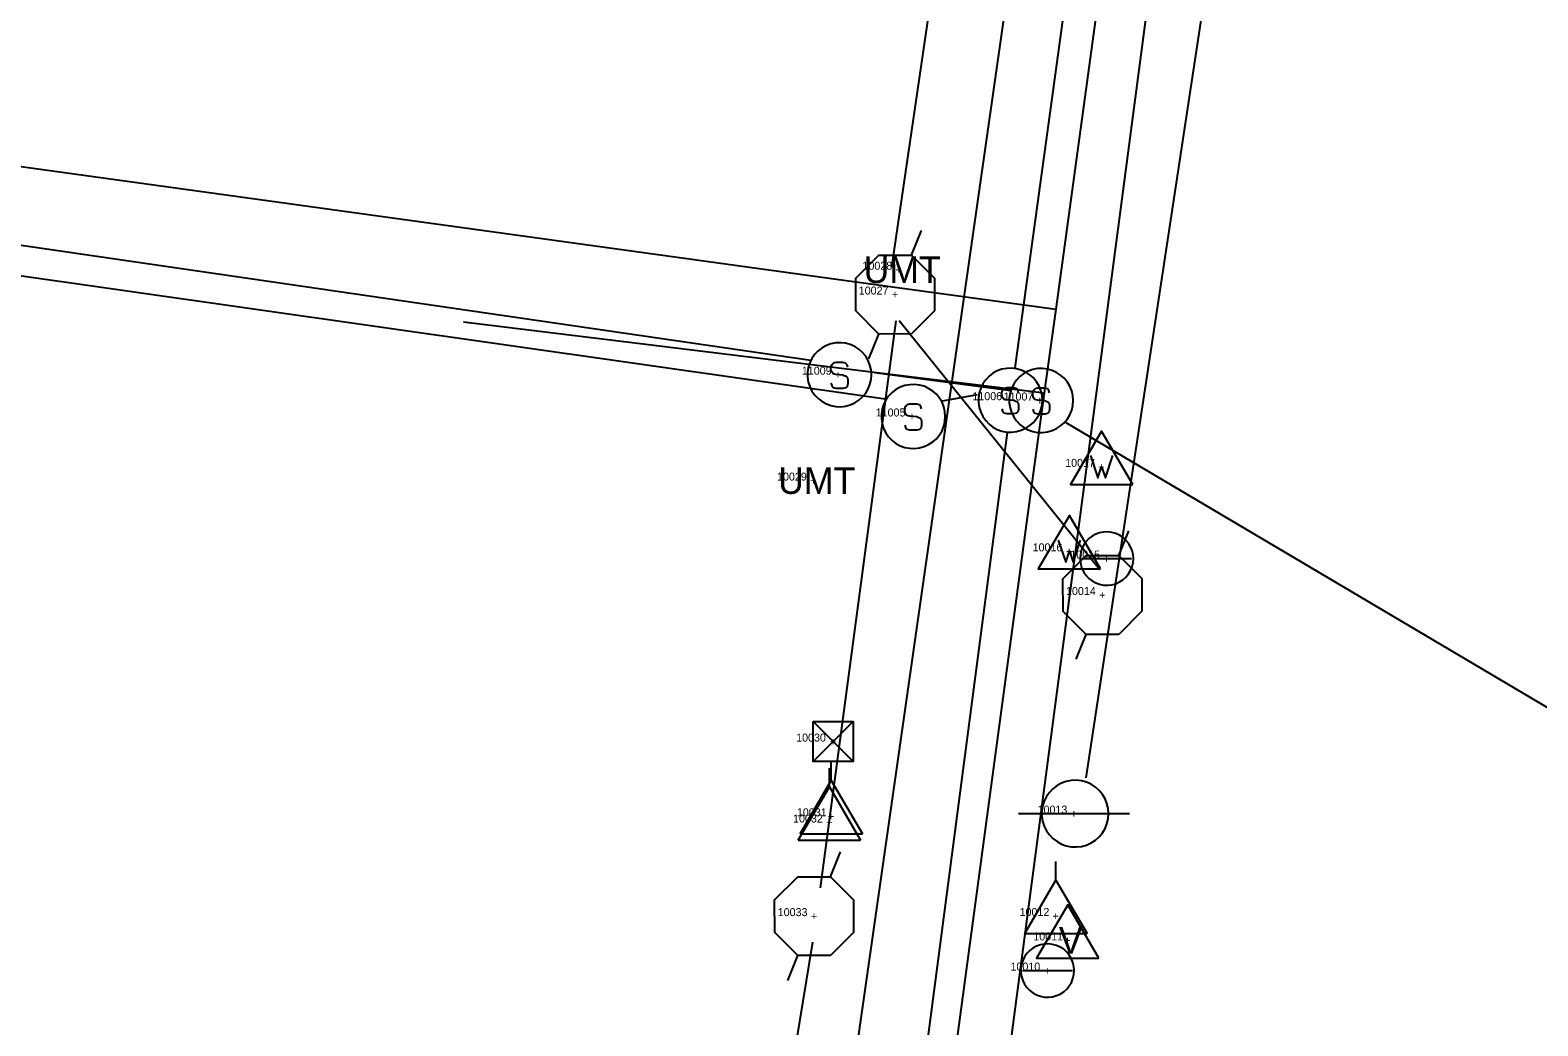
# Model space of a CAD drawing. Extents: x 1795905 to 1799611, y 243768 to 252016.
# Drawn here: x 1797344.4 to 1797626.9, y 244659.6 to 244846.2 of the extents above; entities that cross this region are included whole.
import ezdxf

# ---------------------------------------------------------------- set-up
doc = ezdxf.new("R2010")
doc.units = 0
for name, color, linetype in [('Level 50', 7, 'Continuous'), ('LS-SURVEY POINT', 7, 'Continuous'), ('OHUT', 7, 'Continuous'), ('OHUTTXT', 7, 'Continuous'), ('UGUT', 7, 'Continuous'), ('UGUTTXT', 7, 'Continuous')]:
    doc.layers.add(name, color=color, linetype=linetype)

msp = doc.modelspace()

# ---------------------------------------------------------------- linework, layer by layer
at = {"layer": 'Level 50'}
for p, q in [((1797509.53, 244804.03), (1797511.43, 244808.65)), ((1797501.54, 244784.61), (1797503.44, 244789.23)), ((1797548.38, 244747.73), (1797550.28, 244752.35)), ((1797540.4, 244728.3), (1797542.3, 244732.93)), ((1797494.34, 244687.56), (1797496.25, 244692.19)), ((1797486.36, 244668.14), (1797488.26, 244672.77))]:
    msp.add_line(p, q, dxfattribs=at)
for points in [[(1797509.57, 244789.25), (1797503.44, 244789.23), (1797499.1, 244793.55), (1797499.09, 244799.67), (1797503.4, 244804.01), (1797509.53, 244804.03), (1797513.87, 244799.71), (1797513.89, 244793.59)], [(1797548.42, 244732.95), (1797542.3, 244732.93), (1797537.96, 244737.25), (1797537.94, 244743.37), (1797542.26, 244747.71), (1797548.38, 244747.73), (1797552.72, 244743.41), (1797552.74, 244737.29)], [(1797494.38, 244672.78), (1797488.26, 244672.77), (1797483.92, 244677.08), (1797483.9, 244683.21), (1797488.22, 244687.55), (1797494.34, 244687.56), (1797498.69, 244683.25), (1797498.7, 244677.12)]]:
    msp.add_lwpolyline(points, close=True, dxfattribs=at)
at = {"layer": 'OHUT'}
for p, q in [((1797494.51, 244705.57), (1797494.51, 244709.07)), ((1797494.17, 244704.41), (1797494.17, 244707.91)), ((1797529.59, 244699.38), (1797550.43, 244699.38)), ((1797488.34, 244694.41), (1797500.01, 244694.41)), ((1797488.68, 244695.57), (1797500.35, 244695.57)), ((1797536.63, 244686.89), (1797536.63, 244690.39)), ((1797530.8, 244676.89), (1797542.46, 244676.89))]:
    msp.add_line(p, q, dxfattribs=at)
for points in [[(1797488.68, 244695.57), (1797494.51, 244705.57), (1797500.35, 244695.57)], [(1797488.34, 244694.41), (1797494.17, 244704.41), (1797500.01, 244694.41)], [(1797530.8, 244676.89), (1797536.63, 244686.89), (1797542.46, 244676.89)]]:
    msp.add_lwpolyline(points, dxfattribs=at)
msp.add_lwpolyline([(1797546.47, 244699.38), (1797546.4, 244700.33), (1797546.18, 244701.26), (1797545.82, 244702.15), (1797545.33, 244702.97), (1797544.72, 244703.71), (1797544.01, 244704.35), (1797543.21, 244704.87), (1797542.33, 244705.26), (1797541.41, 244705.51), (1797540.46, 244705.62), (1797539.5, 244705.58), (1797538.56, 244705.4), (1797537.66, 244705.08), (1797536.82, 244704.62), (1797536.06, 244704.04), (1797535.4, 244703.35), (1797534.85, 244702.57), (1797534.42, 244701.71), (1797534.13, 244700.8), (1797533.99, 244699.85), (1797533.99, 244698.9), (1797534.13, 244697.95), (1797534.42, 244697.04), (1797534.85, 244696.18), (1797535.4, 244695.4), (1797536.06, 244694.71), (1797536.82, 244694.13), (1797537.66, 244693.67), (1797538.56, 244693.35), (1797539.5, 244693.17), (1797540.46, 244693.13), (1797541.41, 244693.24), (1797542.33, 244693.49), (1797543.21, 244693.89), (1797544.01, 244694.4), (1797544.72, 244695.04), (1797545.33, 244695.78), (1797545.82, 244696.6), (1797546.18, 244697.49), (1797546.4, 244698.42)], close=True, dxfattribs=at)
at = {"layer": 'OHUTTXT'}
for p, q in [((1797505.88, 244801.76), (1797519.74, 244896.6)), ((1797542.26, 244706.1), (1797564.52, 244852.58)), ((1797492.48, 244685.45), (1797506.67, 244791.73)), ((1797507.22, 244791.74), (1797544.87, 244745.14)), ((1797477.37, 244591.55), (1797491.04, 244675.3))]:
    msp.add_line(p, q, dxfattribs=at)
at = {"layer": 'UGUT'}
for p, q in [((1797494.46, 244782.57), (1797494.46, 244783.02)), ((1797494.59, 244782.12), (1797494.46, 244782.57)), ((1797494.84, 244781.8), (1797494.59, 244782.12)), ((1797495.36, 244781.67), (1797494.84, 244781.8)), ((1797496.76, 244781.55), (1797495.36, 244781.67)), ((1797497.21, 244783.79), (1797496.7, 244783.91)), ((1797497.47, 244783.47), (1797497.21, 244783.79)), ((1797497.6, 244783.02), (1797497.47, 244783.47)), ((1797494.46, 244780.01), (1797494.59, 244779.56)), ((1797494.59, 244779.56), (1797494.84, 244779.24)), ((1797494.84, 244779.24), (1797495.36, 244779.11)), ((1797495.36, 244779.11), (1797496.76, 244779.11)), ((1797496.76, 244781.55), (1797497.28, 244781.35)), ((1797496.76, 244779.11), (1797497.28, 244779.24)), ((1797497.6, 244781.03), (1797497.28, 244781.35)), ((1797497.28, 244779.24), (1797497.6, 244779.56)), ((1797497.66, 244780.59), (1797497.6, 244781.03)), ((1797497.6, 244779.56), (1797497.66, 244780.01)), ((1797497.66, 244780.01), (1797497.66, 244780.59)), ((1797529.25, 244779.01), (1797528.73, 244779.14)), ((1797529.5, 244778.69), (1797529.25, 244779.01)), ((1797535.03, 244778.95), (1797534.51, 244779.08)), ((1797535.28, 244778.63), (1797535.03, 244778.95)), ((1797511.05, 244775.96), (1797510.54, 244776.09)), ((1797526.49, 244777.79), (1797526.49, 244778.24)), ((1797526.62, 244777.35), (1797526.49, 244777.79)), ((1797526.88, 244777.03), (1797526.62, 244777.35)), ((1797527.39, 244776.9), (1797526.88, 244777.03)), ((1797528.8, 244776.77), (1797527.39, 244776.9)), ((1797528.8, 244776.77), (1797529.31, 244776.58)), ((1797529.63, 244776.26), (1797529.31, 244776.58)), ((1797529.63, 244778.24), (1797529.5, 244778.69)), ((1797529.69, 244775.81), (1797529.63, 244776.26)), ((1797532.27, 244777.74), (1797532.27, 244778.18)), ((1797532.4, 244777.29), (1797532.27, 244777.74)), ((1797532.66, 244776.97), (1797532.4, 244777.29)), ((1797533.17, 244776.84), (1797532.66, 244776.97)), ((1797534.58, 244776.71), (1797533.17, 244776.84)), ((1797534.58, 244776.71), (1797535.09, 244776.52)), ((1797535.41, 244776.2), (1797535.09, 244776.52)), ((1797535.41, 244778.18), (1797535.28, 244778.63)), ((1797535.47, 244775.75), (1797535.41, 244776.2)), ((1797508.3, 244774.74), (1797508.3, 244775.19)), ((1797508.43, 244774.29), (1797508.3, 244774.74)), ((1797508.69, 244773.97), (1797508.43, 244774.29)), ((1797509.2, 244773.85), (1797508.69, 244773.97)), ((1797510.61, 244773.72), (1797509.2, 244773.85)), ((1797510.61, 244773.72), (1797511.12, 244773.53)), ((1797511.31, 244775.64), (1797511.05, 244775.96)), ((1797511.44, 244773.21), (1797511.12, 244773.53)), ((1797511.44, 244775.19), (1797511.31, 244775.64)), ((1797511.5, 244772.76), (1797511.44, 244773.21)), ((1797526.49, 244775.23), (1797526.62, 244774.79)), ((1797526.62, 244774.79), (1797526.88, 244774.47)), ((1797526.88, 244774.47), (1797527.39, 244774.34)), ((1797527.39, 244774.34), (1797528.8, 244774.34)), ((1797528.8, 244774.34), (1797529.31, 244774.47)), ((1797529.31, 244774.47), (1797529.63, 244774.79)), ((1797529.63, 244774.79), (1797529.69, 244775.23)), ((1797529.69, 244775.23), (1797529.69, 244775.81)), ((1797532.27, 244775.18), (1797532.4, 244774.73)), ((1797532.4, 244774.73), (1797532.66, 244774.41)), ((1797532.66, 244774.41), (1797533.17, 244774.28)), ((1797533.17, 244774.28), (1797534.58, 244774.28)), ((1797534.58, 244774.28), (1797535.09, 244774.41)), ((1797535.09, 244774.41), (1797535.41, 244774.73)), ((1797535.41, 244774.73), (1797535.47, 244775.18)), ((1797535.47, 244775.18), (1797535.47, 244775.75)), ((1797508.3, 244772.18), (1797508.43, 244771.73)), ((1797508.43, 244771.73), (1797508.69, 244771.41)), ((1797508.69, 244771.41), (1797509.2, 244771.29)), ((1797509.2, 244771.29), (1797510.61, 244771.29)), ((1797510.61, 244771.29), (1797511.12, 244771.41)), ((1797511.12, 244771.41), (1797511.44, 244771.73)), ((1797511.44, 244771.73), (1797511.5, 244772.18)), ((1797511.5, 244772.18), (1797511.5, 244772.76)), ((1797541.46, 244747.16), (1797550.8, 244747.16)), ((1797491.13, 244716.62), (1797498.63, 244709.12)), ((1797498.63, 244716.62), (1797491.13, 244709.12)), ((1797530.38, 244669.97), (1797539.71, 244669.97))]:
    msp.add_line(p, q, dxfattribs=at)
for points in [[(1797502.05, 244781.61), (1797501.98, 244782.52), (1797501.77, 244783.42), (1797501.43, 244784.27), (1797500.96, 244785.06), (1797500.37, 244785.77), (1797499.69, 244786.38), (1797498.92, 244786.88), (1797498.08, 244787.25), (1797497.19, 244787.5), (1797496.28, 244787.6), (1797495.36, 244787.57), (1797494.46, 244787.39), (1797493.6, 244787.08), (1797492.79, 244786.64), (1797492.06, 244786.09), (1797491.42, 244785.43), (1797490.89, 244784.67), (1797490.49, 244783.85), (1797490.21, 244782.97), (1797490.07, 244782.07), (1797490.07, 244781.15), (1797490.21, 244780.24), (1797490.49, 244779.37), (1797490.89, 244778.54), (1797491.42, 244777.79), (1797492.06, 244777.13), (1797492.79, 244776.57), (1797493.6, 244776.13), (1797494.46, 244775.82), (1797495.36, 244775.65), (1797496.28, 244775.61), (1797497.19, 244775.72), (1797498.08, 244775.96), (1797498.92, 244776.34), (1797499.69, 244776.84), (1797500.37, 244777.45), (1797500.96, 244778.16), (1797501.43, 244778.95), (1797501.77, 244779.8), (1797501.98, 244780.69)], [(1797534.09, 244776.83), (1797534.02, 244777.75), (1797533.81, 244778.64), (1797533.46, 244779.49), (1797532.99, 244780.28), (1797532.41, 244780.99), (1797531.72, 244781.6), (1797530.95, 244782.1), (1797530.11, 244782.48), (1797529.23, 244782.72), (1797528.32, 244782.83), (1797527.4, 244782.79), (1797526.5, 244782.62), (1797525.63, 244782.31), (1797524.82, 244781.87), (1797524.09, 244781.31), (1797523.46, 244780.65), (1797522.93, 244779.9), (1797522.52, 244779.07), (1797522.24, 244778.2), (1797522.1, 244777.29), (1797522.1, 244776.37), (1797522.24, 244775.46), (1797522.52, 244774.59), (1797522.93, 244773.77), (1797523.46, 244773.01), (1797524.09, 244772.35), (1797524.82, 244771.8), (1797525.63, 244771.36), (1797526.5, 244771.05), (1797527.4, 244770.87), (1797528.32, 244770.84), (1797529.23, 244770.94), (1797530.11, 244771.19), (1797530.95, 244771.56), (1797531.72, 244772.06), (1797532.41, 244772.67), (1797532.99, 244773.38), (1797533.46, 244774.17), (1797533.81, 244775.02), (1797534.02, 244775.92)], [(1797539.87, 244776.77), (1797539.79, 244777.69), (1797539.59, 244778.58), (1797539.24, 244779.44), (1797538.77, 244780.23), (1797538.19, 244780.94), (1797537.5, 244781.55), (1797536.73, 244782.05), (1797535.89, 244782.42), (1797535.01, 244782.67), (1797534.09, 244782.77), (1797533.18, 244782.74), (1797532.28, 244782.56), (1797531.41, 244782.25), (1797530.6, 244781.81), (1797529.87, 244781.25), (1797529.24, 244780.59), (1797528.71, 244779.84), (1797528.3, 244779.02), (1797528.02, 244778.14), (1797527.88, 244777.23), (1797527.88, 244776.32), (1797528.02, 244775.41), (1797528.3, 244774.53), (1797528.71, 244773.71), (1797529.24, 244772.96), (1797529.87, 244772.3), (1797530.6, 244771.74), (1797531.41, 244771.3), (1797532.28, 244770.99), (1797533.18, 244770.81), (1797534.09, 244770.78), (1797535.01, 244770.89), (1797535.89, 244771.13), (1797536.73, 244771.5), (1797537.5, 244772), (1797538.19, 244772.61), (1797538.77, 244773.32), (1797539.24, 244774.11), (1797539.59, 244774.96), (1797539.79, 244775.86)], [(1797515.89, 244773.78), (1797515.82, 244774.7), (1797515.61, 244775.59), (1797515.27, 244776.44), (1797514.8, 244777.23), (1797514.22, 244777.94), (1797513.53, 244778.55), (1797512.76, 244779.05), (1797511.92, 244779.43), (1797511.04, 244779.67), (1797510.12, 244779.78), (1797509.21, 244779.74), (1797508.3, 244779.57), (1797507.44, 244779.26), (1797506.63, 244778.82), (1797505.9, 244778.26), (1797505.26, 244777.6), (1797504.74, 244776.85), (1797504.33, 244776.02), (1797504.05, 244775.15), (1797503.91, 244774.24), (1797503.91, 244773.32), (1797504.05, 244772.41), (1797504.33, 244771.54), (1797504.74, 244770.71), (1797505.26, 244769.96), (1797505.9, 244769.3), (1797506.63, 244768.74), (1797507.44, 244768.31), (1797508.3, 244767.99), (1797509.21, 244767.82), (1797510.12, 244767.79), (1797511.04, 244767.89), (1797511.92, 244768.13), (1797512.76, 244768.51), (1797513.53, 244769.01), (1797514.22, 244769.62), (1797514.8, 244770.33), (1797515.27, 244771.12), (1797515.61, 244771.97), (1797515.82, 244772.86)], [(1797551.01, 244761.04), (1797545.18, 244771.04), (1797539.35, 244761.04)], [(1797544.98, 244745.21), (1797539.14, 244755.21), (1797533.31, 244745.21)], [(1797551.13, 244747.16), (1797551.07, 244747.92), (1797550.9, 244748.67), (1797550.61, 244749.38), (1797550.22, 244750.04), (1797549.73, 244750.63), (1797549.16, 244751.14), (1797548.52, 244751.55), (1797547.82, 244751.86), (1797547.08, 244752.07), (1797546.32, 244752.15), (1797545.56, 244752.13), (1797544.81, 244751.98), (1797544.09, 244751.72), (1797543.41, 244751.36), (1797542.8, 244750.89), (1797542.27, 244750.34), (1797541.83, 244749.71), (1797541.49, 244749.03), (1797541.26, 244748.3), (1797541.15, 244747.54), (1797541.15, 244746.78), (1797541.26, 244746.02), (1797541.49, 244745.29), (1797541.83, 244744.6), (1797542.27, 244743.98), (1797542.8, 244743.43), (1797543.41, 244742.96), (1797544.09, 244742.6), (1797544.81, 244742.34), (1797545.56, 244742.19), (1797546.32, 244742.16), (1797547.08, 244742.25), (1797547.82, 244742.45), (1797548.52, 244742.77), (1797549.16, 244743.18), (1797549.73, 244743.69), (1797550.22, 244744.28), (1797550.61, 244744.94), (1797550.9, 244745.65), (1797551.07, 244746.4)], [(1797491.13, 244716.62), (1797498.63, 244716.62), (1797498.63, 244709.12), (1797491.13, 244709.12)], [(1797544.66, 244672.29), (1797538.83, 244682.29), (1797533, 244672.29)], [(1797540.04, 244669.97), (1797539.99, 244670.73), (1797539.81, 244671.48), (1797539.52, 244672.19), (1797539.13, 244672.85), (1797538.65, 244673.44), (1797538.07, 244673.95), (1797537.43, 244674.36), (1797536.73, 244674.68), (1797536, 244674.88), (1797535.24, 244674.97), (1797534.47, 244674.94), (1797533.72, 244674.79), (1797533, 244674.53), (1797532.32, 244674.17), (1797531.72, 244673.7), (1797531.19, 244673.15), (1797530.75, 244672.53), (1797530.41, 244671.84), (1797530.18, 244671.11), (1797530.06, 244670.35), (1797530.06, 244669.59), (1797530.18, 244668.83), (1797530.41, 244668.1), (1797530.75, 244667.42), (1797531.19, 244666.79), (1797531.72, 244666.24), (1797532.32, 244665.77), (1797533, 244665.41), (1797533.72, 244665.15), (1797534.47, 244665), (1797535.24, 244664.98), (1797536, 244665.06), (1797536.73, 244665.27), (1797537.43, 244665.58), (1797538.07, 244665.99), (1797538.65, 244666.5), (1797539.13, 244667.09), (1797539.52, 244667.75), (1797539.81, 244668.46), (1797539.99, 244669.21)]]:
    msp.add_lwpolyline(points, close=True, dxfattribs=at)
for points in [[(1797494.46, 244783.02), (1797494.59, 244783.47), (1797494.84, 244783.79)], [(1797496.7, 244783.91), (1797495.36, 244783.91), (1797494.84, 244783.79)], [(1797526.49, 244778.24), (1797526.62, 244778.69), (1797526.88, 244779.01)], [(1797528.73, 244779.14), (1797527.39, 244779.14), (1797526.88, 244779.01)], [(1797532.27, 244778.18), (1797532.4, 244778.63), (1797532.66, 244778.95)], [(1797534.51, 244779.08), (1797533.17, 244779.08), (1797532.66, 244778.95)], [(1797510.54, 244776.09), (1797509.2, 244776.09), (1797508.69, 244775.96)], [(1797508.3, 244775.19), (1797508.43, 244775.64), (1797508.69, 244775.96)], [(1797543.1, 244766.46), (1797544.49, 244762.29), (1797545.18, 244764.37), (1797545.88, 244762.29), (1797547.26, 244766.46)], [(1797537.06, 244750.63), (1797538.45, 244746.46), (1797539.14, 244748.55), (1797539.84, 244746.46), (1797541.23, 244750.63)]]:
    msp.add_lwpolyline(points, dxfattribs=at)
at = {"layer": 'UGUTTXT'}
for p, q in [((1797473.84, 244476.69), (1797534.35, 244900.9)), ((1797504.59, 244777.04), (1797165.71, 244825.29)), ((1797490.66, 244784.27), (1797217.66, 244824.02)), ((1797502.64, 244781.99), (1797528.19, 244778.64)), ((1797521.85, 244777.82), (1797515.33, 244776.64)), ((1797481.84, 244422.43), (1797527.52, 244770.8)), ((1797538.45, 244772.67), (1797724.88, 244662.3))]:
    msp.add_line(p, q, dxfattribs=at)
for points in [[(1797528.99, 244782.88), (1797605.53, 245339.83), (1797411.24, 245347.9)], [(1797609.06, 245323.62), (1797536.58, 244793.88)], [(1797530.89, 244677.28), (1797558.11, 244883.23), (1797570.29, 244971.44)], [(1797180.76, 244842.97), (1797494.09, 244799.69)], [(1797494.09, 244799.69), (1797536.58, 244793.88)], [(1797494.09, 244799.69), (1797536.58, 244793.88)], [(1797536.58, 244793.88), (1797534.44, 244778.2)], [(1797425.59, 244791.51), (1797508.68, 244781.35)], [(1797508.68, 244781.35), (1797534.44, 244778.2)], [(1797534.44, 244778.2), (1797531.25, 244754.88)], [(1797531.25, 244754.88), (1797497.75, 244506.39)], [(1797502.73, 244464.27), (1797530.89, 244677.28)]]:
    msp.add_lwpolyline(points, dxfattribs=at)

# ---------------------------------------------------------------- texts
at = {"layer": 'LS-SURVEY POINT'}
for s, p in [('10028', (1797500.36, 244801.27)), ('+', (1797506.56, 244800.52)), ('10027', (1797499.66, 244796.63)), ('+', (1797505.86, 244795.88)), ('11009', (1797489, 244781.61)), ('+', (1797495.2, 244780.86)), ('11006', (1797520.96, 244776.83)), ('11007', (1797526.81, 244776.77)), ('+', (1797527.23, 244776.08)), ('+', (1797533.01, 244776.02)), ('11005', (1797502.84, 244773.78)), ('+', (1797509.04, 244773.03)), ('10017', (1797538.35, 244764.34)), ('+', (1797544.56, 244763.59)), ('10029', (1797484.35, 244761.77)), ('+', (1797490.55, 244761.02)), ('10016', (1797532.25, 244748.51)), ('+', (1797538.52, 244747.76)), ('10015', (1797539.3, 244747.16)), ('+', (1797545.51, 244746.41)), ('10014', (1797538.51, 244740.33)), ('+', (1797544.71, 244739.58)), ('10030', (1797487.93, 244712.87)), ('+', (1797494.25, 244712.12)), ('10031', (1797488.07, 244698.87)), ('10013', (1797533.18, 244699.38)), ('+', (1797539.39, 244698.63)), ('10032', (1797487.35, 244697.71)), ('+', (1797493.55, 244696.96)), ('+', (1797493.89, 244698.12)), ('10033', (1797484.48, 244680.17)), ('+', (1797490.68, 244679.42)), ('10012', (1797529.8, 244680.19)), ('+', (1797536, 244679.44)), ('10011', (1797532.38, 244675.62)), ('+', (1797538.2, 244674.87)), ('10010', (1797528.1, 244669.97)), ('+', (1797534.42, 244669.22))]:
    msp.add_text(s, height=1.5, dxfattribs=at).set_placement(p)
at = {"layer": 'UGUT'}
for p in [(1797500.56, 244798.77), (1797484.55, 244759.27)]:
    msp.add_text('UMT', height=5, dxfattribs=at).set_placement(p)
for s, height, p in [('+', 1, (1797494.45, 244712.37)), ('V', 5, (1797537.16, 244673.12)), ('+', 0.1, (1797538.79, 244675.57))]:
    msp.add_text(s, height=height, rotation=360, dxfattribs=at).set_placement(p)

doc.saveas('drawing.dxf')
